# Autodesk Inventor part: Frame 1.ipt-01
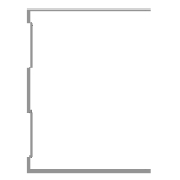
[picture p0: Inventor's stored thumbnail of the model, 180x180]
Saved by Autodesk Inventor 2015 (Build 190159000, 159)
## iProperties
Created: 2015-04
Part Number: Frame 1.ipt-01
Material: Aluminum 6061
Document SubType Name: Modeling
Standard: Unnamed
Designer: suporte
Language: en-US
Size Designation: (Unnamed 1)
Categories: <MemberInstance><Categories><Category DisplayName="Structural Shapes" InternalName="089c4875-fa83-4c05-b084-43b9cc11f5ed" Mnemonic="GRDR"><CategoryParameter Dis
Density: 2.7 g/cm^3
Appearance: Aluminum - Flat
IsCustomPart: 1
G_L: 224,820 mm
G_W: 70,000 mm
G_H: 75,000 mm
+BD433694-75ED-40FA-B604-0D23CBD579F9+CUTDETAIL1: Miter 67,49 deg
_CCFamilyMember: 1
_CCFamilyDisplayName: Frame 1
_FrameMemberDoc: Frame Member File
_Version: 15.0.0
_GetPNFromCC: 1
Author: suporte
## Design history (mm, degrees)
node "Start Plane"
node "End Plane"
sketch "Sketch"
  geometry: L1 (34.6, 37.5)-(34.6, 36.7); L2 (34.6, 36.7)-(-34.6, 36.7); L3 (-34.6, -36.7)-(34.6, -36.7); L4 (34.6, -36.7)-(34.6, -37.5); L5 (34.6, -37.5)-(-35.4, -37.5); L6 (-35.4, 37.5)-(34.6, 37.5); L7 (-34.6, 36.7)-(-34.6, 31.7); L8 (-34.6, 31.7)-(-33.4, 30.5); L9 (-33.4, 30.5)-(-33.4, 10.746); L10 (-33.4, 10.746)-(-34.6, 9.546); L11 (-34.6, 9.546)-(-34.6, -9.546); L12 (-34.6, -9.546)-(-33.4, -10.746); L13 (-33.4, -10.746)-(-33.4, -30.5); L14 (-33.4, -30.5)-(-34.6, -31.7); L15 (-34.6, -31.7)-(-34.6, -36.7); L16 (-35.4, -37.5)-(-35.4, -31.369); L17 (-35.4, -31.369)-(-34.2, -30.169); L18 (-34.2, -30.169)-(-34.2, -11.077); L19 (-34.2, -11.077)-(-35.4, -9.877); L20 (-35.4, -9.877)-(-35.4, 9.877); L21 (-35.4, 9.877)-(-34.2, 11.077); L22 (-34.2, 11.077)-(-34.2, 30.169); L23 (-34.2, 30.169)-(-35.4, 31.369); L24 (-35.4, 31.369)-(-35.4, 37.5); L25 (-35.4, 0)-(30.37, 0); 3 further points
  constraints: 50 end point, 10 point on line, 9 parallel, 5 perpendicular, 4 equal length, 3 midpoint, 3 vertical, 2 vertical alignment, 1 collinear, 1 horizontal, 1 horizontal alignment
  dimensions: "d3" = 0.8 distance of L1.start L1.end; "d5" = 75 distance between parallel lines of L5 L6; "d6" = 0.8 distance between parallel lines of L24 L7; "d7" = 0.8 distance between parallel lines of L8 L23; "d8" = 0.8 distance between parallel lines of L22 L9; "d9" = 0.8 distance between parallel lines of L17 L14; "d10" = 0.8 distance between parallel lines of L13 L18; "d11" = 0.8 distance between parallel lines of L12 L19; "d12" = 0.8 distance between parallel lines of L21 L10; "d13" = 5 distance of L2.end L7.end; "d15" = 135 deg angle of L9 L8; "d16" = 2 distance between parallel lines of L24 L9; "d17" = 70 distance of L6.start L1.start
extrude "Body" join sketch "Sketch" stored distance "d24" = 0.13; taper "d25" = 0 deg
node "Driven Length"
  sketch "Sketch8"
    geometry: L1 (0, 0)-(10, 0) reference
    constraints: 2 end point, 1 horizontal
  workplane "Work Plane6"
  sketch "Sketch9"
    geometry: L1 (-2, 0)-(12, 0) reference; L2 (-2, 224.82)-(12, 224.82) reference
    dimensions: "d27" = 224.81978 distance between parallel lines of L1 L2 (derived)
workplane "Work Plane7"
split "Split1"
body "Solid1"
other parameters: "tamanho" = 188.55826, "G_OFFSET_START" = 0 [user parameter; used in 1 equation term], "G_OFFSET_END" = 36.26152 [user parameter; used in 1 equation term], "d22" = 0 (computed from G_OFFSET_START), "d23" = 224.81978 (= tamanho + G_OFFSET_END), "G_L" = 224.81978 (= d27) [user parameter], "d32" = 90 deg
